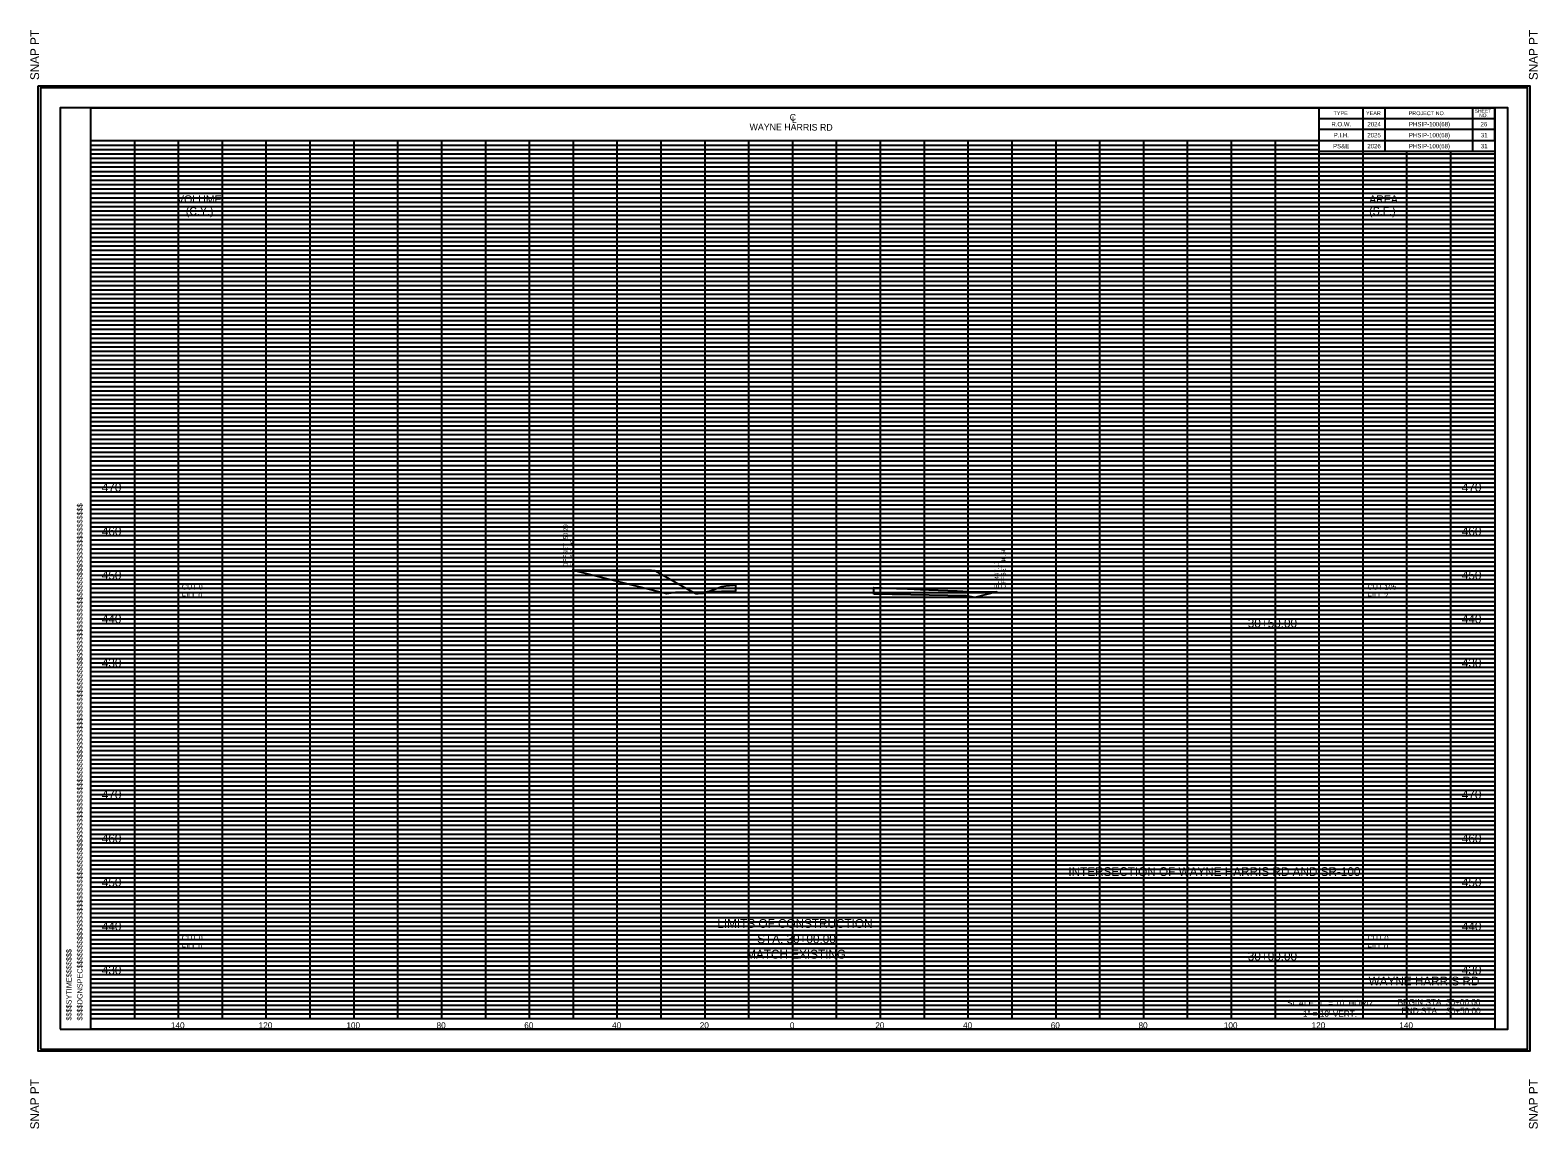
# Model space of a CAD drawing. Extents: x 986 to 1342, y 975 to 1485.
# Drawn here: x 986.2 to 1329.8, y 974.8 to 1225.2 of the extents above; entities that cross this region are included whole.
import ezdxf

# ---------------------------------------------------------------- set-up
doc = ezdxf.new("R2010")
doc.units = 0
for name, color, linetype in [('Default', 7, 'Continuous'), ('DESIGN - DRAINAGE - Special Ditch Width Text', 7, 'Continuous'), ('DESIGN - EARTHWORK - Shapes', 7, 'Continuous'), ('DESIGN - SCRATCH - User 1', 7, 'Continuous'), ('DESIGN - SHEET - Corner Text', 7, 'Continuous'), ('DESIGN - SHEET - Light Grid', 7, 'Continuous'), ('DESIGN - SHEET - Linework', 7, 'Continuous'), ('DESIGN - SHEET - Plot Shape', 7, 'Continuous'), ('DESIGN - TYPICAL - Slope Tie Text', 7, 'Continuous'), ('DESIGN - TYPICAL - Text', 7, 'Continuous')]:
    doc.layers.add(name, color=color, linetype=linetype)

msp = doc.modelspace()

# ---------------------------------------------------------------- linework, layer by layer
at = {"layer": 'DESIGN - EARTHWORK - Shapes'}
for points in [[(1109.71, 1102.09), (1127.78, 1102.1), (1128.55, 1102.05), (1135.91, 1097.86), (1137.23, 1097.11), (1133.26, 1097.03), (1131.26, 1096.7)], [(1137.23, 1097.11), (1140.57, 1097.18), (1139.57, 1096.79), (1138.42, 1096.73), (1137.94, 1096.71)], [(1140.57, 1097.18), (1141.97, 1097.72), (1143.83, 1098.43), (1144.77, 1098.52), (1145.59, 1098.62), (1146.49, 1098.74), (1146.95, 1098.81), (1146.95, 1098.81), (1146.95, 1097.31)], [(1178.5, 1096.67), (1178.5, 1098.17), (1180.35, 1098.09), (1181.54, 1098.04), (1183.67, 1097.95), (1183.96, 1097.94), (1184.45, 1097.92), (1186.13, 1097.85), (1189.15, 1097.72), (1191.01, 1097.64), (1197.47, 1097.38), (1200.12, 1097.27), (1203.92, 1097.18), (1206.5, 1097.17), (1201.49, 1095.92), (1199.49, 1096.25)]]:
    msp.add_lwpolyline(points, close=True, dxfattribs=at)
at = {"layer": 'DESIGN - SCRATCH - User 1'}
for p, q in [((1285, 1203.75), (1285, 1203.75)), ((1292.5, 1203.75), (1292.5, 1203.75)), ((1305, 1203.75), (1305, 1203.75)), ((1317.5, 1203.75), (1317.5, 1203.75)), ((1285, 1201.25), (1285, 1201.25)), ((1292.5, 1201.25), (1292.5, 1201.25)), ((1305, 1201.25), (1305, 1201.25)), ((1317.5, 1201.25), (1317.5, 1201.25)), ((1000, 1000), (1000, 1000))]:
    msp.add_line(p, q, dxfattribs=at)
at = {"layer": 'DESIGN - SHEET - Light Grid'}
for p, q in [((1000, 1199), (1280, 1199)), ((1000, 1198), (1280, 1198)), ((1000, 1197), (1320, 1197)), ((1000, 1196), (1320, 1196)), ((1000, 1195), (1320, 1195)), ((1000, 1194), (1320, 1194)), ((1000, 1193), (1320, 1193)), ((1000, 1192), (1320, 1192)), ((1000, 1191), (1320, 1191)), ((1000, 1189), (1320, 1189)), ((1000, 1188), (1320, 1188)), ((1000, 1187), (1320, 1187)), ((1000, 1186), (1320, 1186)), ((1000, 1185), (1320, 1185)), ((1000, 1184), (1320, 1184)), ((1000, 1183), (1320, 1183)), ((1000, 1182), (1320, 1182)), ((1000, 1181), (1320, 1181)), ((1000, 1179), (1320, 1179)), ((1000, 1178), (1320, 1178)), ((1000, 1177), (1320, 1177)), ((1000, 1176), (1320, 1176)), ((1000, 1175), (1320, 1175)), ((1000, 1174), (1320, 1174)), ((1000, 1173), (1320, 1173)), ((1000, 1172), (1320, 1172)), ((1000, 1171), (1320, 1171)), ((1000, 1169), (1320, 1169)), ((1000, 1168), (1320, 1168)), ((1000, 1167), (1320, 1167)), ((1000, 1166), (1320, 1166)), ((1000, 1165), (1320, 1165)), ((1000, 1164), (1320, 1164)), ((1000, 1163), (1320, 1163)), ((1000, 1162), (1320, 1162)), ((1000, 1161), (1320, 1161)), ((1000, 1159), (1320, 1159)), ((1000, 1158), (1320, 1158)), ((1000, 1157), (1320, 1157)), ((1000, 1156), (1320, 1156)), ((1000, 1155), (1320, 1155)), ((1000, 1154), (1320, 1154)), ((1000, 1153), (1320, 1153)), ((1000, 1152), (1320, 1152)), ((1000, 1151), (1320, 1151)), ((1000, 1149), (1320, 1149)), ((1000, 1148), (1320, 1148)), ((1000, 1147), (1320, 1147)), ((1000, 1146), (1320, 1146)), ((1000, 1145), (1320, 1145)), ((1000, 1144), (1320, 1144)), ((1000, 1143), (1320, 1143)), ((1000, 1142), (1320, 1142)), ((1000, 1141), (1320, 1141)), ((1000, 1139), (1320, 1139)), ((1000, 1138), (1320, 1138)), ((1000, 1137), (1320, 1137)), ((1000, 1136), (1320, 1136)), ((1000, 1135), (1320, 1135)), ((1000, 1134), (1320, 1134)), ((1000, 1133), (1320, 1133)), ((1000, 1132), (1320, 1132)), ((1000, 1131), (1320, 1131)), ((1000, 1129), (1320, 1129)), ((1000, 1128), (1320, 1128)), ((1000, 1127), (1320, 1127)), ((1000, 1126), (1320, 1126)), ((1000, 1125), (1320, 1125)), ((1000, 1124), (1320, 1124)), ((1000, 1123), (1320, 1123)), ((1000, 1122), (1320, 1122)), ((1000, 1121), (1320, 1121)), ((1000, 1119), (1320, 1119)), ((1000, 1118), (1320, 1118)), ((1000, 1117), (1320, 1117)), ((1000, 1116), (1320, 1116)), ((1000, 1115), (1320, 1115)), ((1000, 1114), (1320, 1114)), ((1000, 1113), (1320, 1113)), ((1000, 1112), (1320, 1112)), ((1000, 1111), (1320, 1111)), ((1000, 1109), (1320, 1109)), ((1000, 1108), (1320, 1108)), ((1000, 1107), (1320, 1107)), ((1000, 1106), (1320, 1106)), ((1000, 1105), (1320, 1105)), ((1000, 1104), (1320, 1104)), ((1000, 1103), (1320, 1103)), ((1000, 1102), (1320, 1102)), ((1000, 1101), (1320, 1101)), ((1000, 1099), (1320, 1099)), ((1000, 1098), (1320, 1098)), ((1000, 1097), (1320, 1097)), ((1000, 1096), (1320, 1096)), ((1000, 1095), (1320, 1095)), ((1000, 1094), (1320, 1094)), ((1000, 1093), (1320, 1093)), ((1000, 1092), (1320, 1092)), ((1000, 1091), (1320, 1091)), ((1000, 1089), (1320, 1089)), ((1000, 1088), (1320, 1088)), ((1000, 1087), (1320, 1087)), ((1000, 1086), (1320, 1086)), ((1000, 1085), (1320, 1085)), ((1000, 1084), (1320, 1084)), ((1000, 1083), (1320, 1083)), ((1000, 1082), (1320, 1082)), ((1000, 1081), (1320, 1081)), ((1000, 1079), (1320, 1079)), ((1000, 1078), (1320, 1078)), ((1000, 1077), (1320, 1077)), ((1000, 1076), (1320, 1076)), ((1000, 1075), (1320, 1075)), ((1000, 1074), (1320, 1074)), ((1000, 1073), (1320, 1073)), ((1000, 1072), (1320, 1072)), ((1000, 1071), (1320, 1071)), ((1000, 1069), (1320, 1069)), ((1000, 1068), (1320, 1068)), ((1000, 1067), (1320, 1067)), ((1000, 1066), (1320, 1066)), ((1000, 1065), (1320, 1065)), ((1000, 1064), (1320, 1064)), ((1000, 1063), (1320, 1063)), ((1000, 1062), (1320, 1062)), ((1000, 1061), (1320, 1061)), ((1000, 1059), (1320, 1059)), ((1000, 1058), (1320, 1058)), ((1000, 1057), (1320, 1057)), ((1000, 1056), (1320, 1056)), ((1000, 1055), (1320, 1055)), ((1000, 1054), (1320, 1054)), ((1000, 1053), (1320, 1053)), ((1000, 1052), (1320, 1052)), ((1000, 1051), (1320, 1051)), ((1000, 1049), (1320, 1049)), ((1000, 1048), (1320, 1048)), ((1000, 1047), (1320, 1047)), ((1000, 1046), (1320, 1046)), ((1000, 1045), (1320, 1045)), ((1000, 1044), (1320, 1044)), ((1000, 1043), (1320, 1043)), ((1000, 1042), (1320, 1042)), ((1000, 1041), (1320, 1041)), ((1000, 1039), (1320, 1039)), ((1000, 1038), (1320, 1038)), ((1000, 1037), (1320, 1037)), ((1000, 1036), (1320, 1036)), ((1000, 1035), (1320, 1035)), ((1000, 1034), (1320, 1034)), ((1000, 1033), (1320, 1033)), ((1000, 1032), (1320, 1032)), ((1000, 1031), (1320, 1031)), ((1000, 1029), (1320, 1029)), ((1000, 1028), (1320, 1028)), ((1000, 1027), (1320, 1027)), ((1000, 1026), (1320, 1026)), ((1000, 1025), (1320, 1025)), ((1000, 1024), (1320, 1024)), ((1000, 1023), (1320, 1023)), ((1000, 1022), (1320, 1022)), ((1000, 1021), (1320, 1021)), ((1000, 1019), (1320, 1019)), ((1000, 1018), (1320, 1018)), ((1000, 1017), (1320, 1017)), ((1000, 1016), (1320, 1016)), ((1000, 1015), (1320, 1015)), ((1000, 1014), (1320, 1014)), ((1000, 1013), (1320, 1013)), ((1000, 1012), (1320, 1012)), ((1000, 1011), (1320, 1011)), ((1000, 1009), (1320, 1009)), ((1000, 1008), (1320, 1008)), ((1000, 1007), (1320, 1007)), ((1000, 1006), (1320, 1006)), ((1000, 1005), (1320, 1005)), ((1000, 1004), (1320, 1004)), ((1000, 1003), (1320, 1003)), ((1000, 1002), (1320, 1002)), ((1000, 1001), (1320, 1001))]:
    msp.add_line(p, q, dxfattribs=at)
at = {"layer": 'DESIGN - SHEET - Linework'}
for p, q in [((1320, 1207.5), (1280, 1207.5)), ((1280, 1200), (1280, 1207.5)), ((1290, 1200), (1290, 1207.5)), ((1295, 1197.5), (1295, 1207.5)), ((1315, 1197.5), (1315, 1207.5)), ((1320, 1200), (1320, 1207.5)), ((1320, 1205), (1280, 1205)), ((1000, 1200), (1320, 1200)), ((1010, 1000), (1010, 1200)), ((1020, 1000), (1020, 1200)), ((1030, 1000), (1030, 1200)), ((1040, 1000), (1040, 1200)), ((1050, 1000), (1050, 1200)), ((1060, 1000), (1060, 1200)), ((1070, 1000), (1070, 1200)), ((1080, 1000), (1080, 1200)), ((1090, 1000), (1090, 1200)), ((1100, 1000), (1100, 1200)), ((1110, 1000), (1110, 1200)), ((1120, 1000), (1120, 1200)), ((1130, 1000), (1130, 1200)), ((1140, 1000), (1140, 1200)), ((1150, 1000), (1150, 1200)), ((1160, 1000), (1160, 1200)), ((1170, 1000), (1170, 1200)), ((1180, 1000), (1180, 1200)), ((1190, 1000), (1190, 1200)), ((1200, 1000), (1200, 1200)), ((1210, 1000), (1210, 1200)), ((1220, 1000), (1220, 1200)), ((1230, 1000), (1230, 1200)), ((1240, 1000), (1240, 1200)), ((1250, 1000), (1250, 1200)), ((1260, 1000), (1260, 1200)), ((1270, 1000), (1270, 1200)), ((1320, 1202.5), (1280, 1202.5)), ((1280, 1000), (1280, 1200)), ((1290, 1000), (1290, 1200)), ((1320, 1197.5), (1280, 1197.5)), ((1300, 1000), (1300, 1197.5)), ((1310, 1000), (1310, 1197.5)), ((1000, 1190), (1320, 1190)), ((1000, 1180), (1320, 1180)), ((1000, 1170), (1320, 1170)), ((1000, 1160), (1320, 1160)), ((1000, 1150), (1320, 1150)), ((1000, 1140), (1320, 1140)), ((1000, 1130), (1320, 1130)), ((1000, 1120), (1320, 1120)), ((1000, 1110), (1320, 1110)), ((1000, 1100), (1320, 1100)), ((1000, 1090), (1320, 1090)), ((1000, 1080), (1320, 1080)), ((1000, 1070), (1320, 1070)), ((1000, 1060), (1320, 1060)), ((1000, 1050), (1320, 1050)), ((1000, 1040), (1320, 1040)), ((1000, 1030), (1320, 1030)), ((1000, 1020), (1320, 1020)), ((1000, 1010), (1320, 1010)), ((1000, 1000), (1320, 1000))]:
    msp.add_line(p, q, dxfattribs=at)
for points in [[(988, 1212.5), (1328, 1212.5), (1328, 992.5), (988, 992.5)], [(1000, 1207.5), (1320, 1207.5), (1320, 997.5), (1000, 997.5)]]:
    msp.add_lwpolyline(points, close=True, dxfattribs=at)
at = {"layer": 'DESIGN - SHEET - Plot Shape'}
for points in [[(988.5, 993), (1327.5, 993), (1327.5, 1212), (988.5, 1212)], [(993, 997.5), (1323, 997.5), (1323, 1207.5), (993, 1207.5)]]:
    msp.add_lwpolyline(points, close=True, dxfattribs=at)

# ---------------------------------------------------------------- texts
at = {"layer": 'Default'}
for s, height, p in [('     470     ', 2, (998.79, 1120)), ('     470     ', 2, (1308.79, 1120)), ('     460     ', 2, (998.79, 1110)), ('     460     ', 2, (1308.79, 1110)), ('     450     ', 2, (998.79, 1100)), ('     450     ', 2, (1308.79, 1100)), ('     440     ', 2, (998.79, 1090)), ('     30+50.00     ', 2, (1260, 1089.04)), ('     440     ', 2, (1308.79, 1090)), ('     430     ', 2, (998.79, 1080)), ('     430     ', 2, (1308.79, 1080)), ('     470     ', 2, (998.79, 1050)), ('     470     ', 2, (1308.79, 1050)), ('     460     ', 2, (998.79, 1040)), ('     460     ', 2, (1308.79, 1040)), ('     450     ', 2, (998.79, 1030)), ('     450     ', 2, (1308.79, 1030)), ('     440     ', 2, (998.79, 1020)), ('     440     ', 2, (1308.79, 1020)), ('     30+00.00     ', 2, (1260, 1013.15)), ('     430     ', 2, (998.79, 1010)), ('     430     ', 2, (1308.79, 1010)), ('     140     ', 1.4, (1015.65, 997.7)), ('     120     ', 1.4, (1035.65, 997.7)), ('     100     ', 1.4, (1055.65, 997.7)), ('     80     ', 1.4, (1076.2, 997.7)), ('     60     ', 1.4, (1096.2, 997.7)), ('     40     ', 1.4, (1116.2, 997.7)), ('     20     ', 1.4, (1136.2, 997.7)), ('     0     ', 1.4, (1156.74, 997.7)), ('     0     ', 1.4, (1156.74, 997.7)), ('     20     ', 1.4, (1176.2, 997.7)), ('     40     ', 1.4, (1196.2, 997.7)), ('     60     ', 1.4, (1216.2, 997.7)), ('     80     ', 1.4, (1236.2, 997.7)), ('     100     ', 1.4, (1255.65, 997.7)), ('     120     ', 1.4, (1275.65, 997.7)), ('     140     ', 1.4, (1295.65, 997.7))]:
    msp.add_text(s, height=height, dxfattribs=at).set_placement(p)
at = {"layer": 'DESIGN - DRAINAGE - Special Ditch Width Text'}
for s, p in [('WAYNE HARRIS RD', (1150.15, 1202.38)), ('C', (1159.29, 1204.58)), ('L', (1159.79, 1204.03))]:
    msp.add_text(s, height=1.5, rotation=359.6675, dxfattribs=at).set_placement(p)
at = {"layer": 'DESIGN - SHEET - Corner Text'}
for s, height, p in [('  SNAP PT', 2, (988.2, 1212.3)), ('  SNAP PT', 2, (1329.8, 1212.3)), ('$$$$DGNSPEC$$$$$$$$$$$$$$$$$$$$$$$$$$$$$$$$$$$$$$$$$$$$$$$$$$$$$$$$$$$$$$$$$$$$$$$$$$$$$$$$$$$$$$$$$$$$$$$$$$$$$$$$$$$$$$$$$$$', 1.2, (998.1, 999.5)), ('$$$$SYTIME$$$$$$$', 1.2, (995.6, 999.5)), ('SNAP PT  ', 2, (988.2, 974.7)), ('SNAP PT  ', 2, (1329.8, 974.7))]:
    msp.add_text(s, height=height, rotation=90, dxfattribs=at).set_placement(p)
for s, height, p in [('R.O.W.', 1, (1282.77, 1203.25)), ('2024', 1, (1290.98, 1203.25)), ('PHSIP-100(68)', 1, (1300.45, 1203.25)), ('26', 1, (1316.75, 1203.25)), ('P.I.H.', 1, (1283.3, 1200.75)), ('2025', 1, (1290.96, 1200.75)), ('PHSIP-100(68)', 1, (1300.43, 1200.75)), ('31', 1, (1316.84, 1200.75)), ('PS&E', 1, (1283.16, 1198.25)), ('2026', 1, (1290.96, 1198.25)), ('PHSIP-100(68)', 1, (1300.43, 1198.25)), ('31', 1, (1316.84, 1198.25)), ('WAYNE HARRIS RD', 2, (1291.25, 1007.5)), ('SCALE: 1" = 10\' HORIZ.', 1.4, (1272.65, 1002.8)), ('BEGIN STA. 30+00.00', 1.4, (1297.86, 1003)), ('       1" = 10\' VERT.   ', 1.4, (1272.65, 1000.35)), ('END STA.   30+50.00', 1.4, (1298.73, 1001))]:
    msp.add_text(s, height=height, dxfattribs=at).set_placement(p)
at = {"layer": 'DESIGN - SHEET - Light Grid'}
for s, height, p in [('TYPE', 0.9, (1283.26, 1205.8)), ('YEAR', 0.9, (1290.66, 1205.8)), ('PROJECT NO.', 0.9, (1300.38, 1205.8)), ('SHEET', 0.8, (1315.47, 1206.35)), ('NO.', 0.8, (1316.47, 1205.35))]:
    msp.add_text(s, height=height, dxfattribs=at).set_placement(p)
at = {"layer": 'DESIGN - TYPICAL - Slope Tie Text'}
for s, p in [('OFFSET -50.29', (1108.71, 1102.84)), ('EL.452.09', (1110.21, 1102.84)), ('OFFSET 46.50', (1208.5, 1097.92)), ('EL.447.17', (1207, 1097.92))]:
    msp.add_text(s, height=1, rotation=90, dxfattribs=at).set_placement(p)
at = {"layer": 'DESIGN - TYPICAL - Text'}
for s, height, p in [('VOLUME', 1.8, (1019.65, 1185.73)), ('AREA ', 1.8, (1291.38, 1185.73)), ('   (C.Y.)', 1.8, (1019.65, 1183.03)), ('(S.F.)', 1.8, (1291.38, 1183.03)), ('CUT 0', 1.2, (1020.72, 1097.7)), ('FILL 0', 1.2, (1020.72, 1095.7)), ('CUT 105', 1.2, (1291, 1097.7)), ('FILL 2', 1.2, (1291, 1095.7)), ('INTERSECTION OF WAYNE HARRIS RD AND SR-100', 2, (1222.82, 1032.44)), ('LIMITS OF CONSTRUCTION', 2, (1142.81, 1020.62)), ('CUT 0', 1.2, (1020.72, 1017.72)), ('STA. 30+00.00', 2, (1151.89, 1017.12)), ('CUT 0', 1.2, (1291, 1017.72)), ('FILL 0', 1.2, (1020.72, 1015.72)), ('MATCH EXISTING', 2, (1149.39, 1013.62)), ('FILL 0', 1.2, (1291, 1015.72))]:
    msp.add_text(s, height=height, dxfattribs=at).set_placement(p)

doc.saveas('drawing.dxf')
